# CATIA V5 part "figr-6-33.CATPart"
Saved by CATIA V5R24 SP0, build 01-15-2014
Part number: Part1
Bounding box of the stored display mesh (mm): x -43 to 43, y -66.608 to 66.608, z -13.545 to 13.545
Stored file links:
  D:\KAVITA\CATIA V5-6R2014 Project_ Kavita\CATIA V5-6R2014_partfiles\Partfiles\c06_catia_v5-6r2014_prt\figr-6-33.CATPart
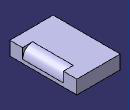
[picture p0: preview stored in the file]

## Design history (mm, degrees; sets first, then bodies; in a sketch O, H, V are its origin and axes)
Body1 (main body)
  Sketch1 on yz-plane, origin (0, 0, 0), H (0, 1, 0), V (0, 0, 1)
    line L1 (-66.6077, 13.5449) -> (66.6077, 13.5449)
    line L2 (66.6077, 13.5449) -> (66.6077, -13.5449)
    line L3 (66.6077, -13.5449) -> (-66.6077, -13.5449)
    line L4 (-66.6077, -13.5449) -> (-66.6077, 13.5449)
    axis line L5 (66.6077, -13.5449) -> (-66.6077, 13.5449)
    horizontal: L1 H, L3 H
    vertical: L2 V, L4 V
    midpoint: O L5
  Pad1: profile Sketch1, direction (1, 0, 0), length 43, mirrored extent
  Fillet1: radius 20, on edge [face of Pad1 | face of Pad1]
